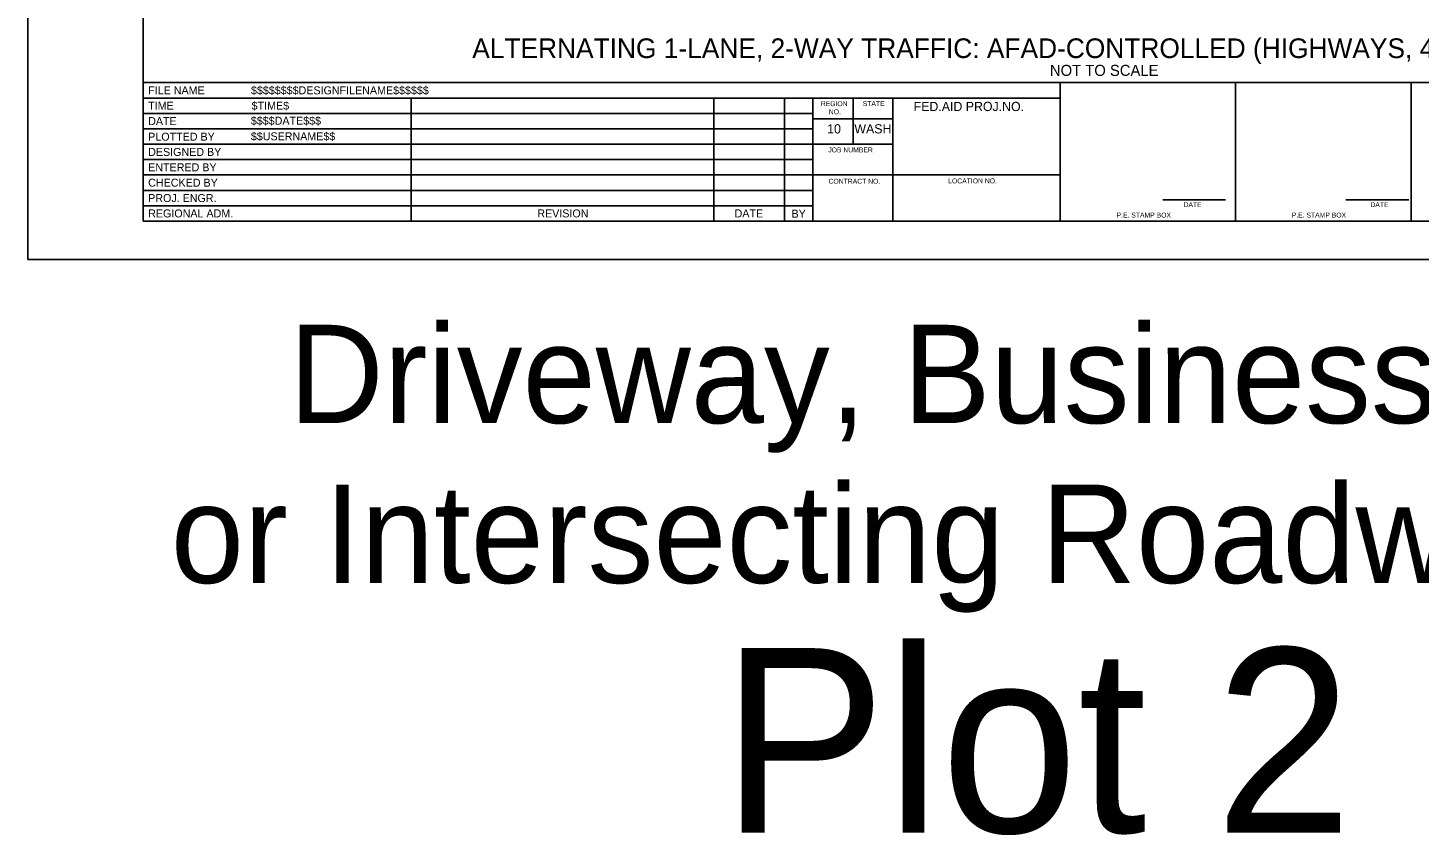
# Model space of a CAD drawing. Extents: x 99999.1 to 100095.7, y 99995 to 100010.7.
# Drawn here: x 100019.06 to 100030.38, y 99995.01 to 100001.57 of the extents above; entities that cross this region are included whole.
import ezdxf

# ---------------------------------------------------------------- set-up
doc = ezdxf.new("R2010")
doc.units = 0
for name, color, linetype in [('SH_DE_DetailHeading1Text', 7, 'Continuous'), ('SH_GI_PlotLimits', 7, 'Continuous'), ('SH_GI_SheetBorder', 7, 'Continuous'), ('SH_GI_SheetLocationText', 7, 'Continuous'), ('SH_GI_SheetTextInCells', 7, 'Continuous'), ('SH_GI_TitleBlockText', 7, 'Continuous')]:
    doc.layers.add(name, color=color, linetype=linetype)

msp = doc.modelspace()

# ---------------------------------------------------------------- linework, layer by layer
at = {"layer": 'SH_GI_PlotLimits'}
msp.add_lwpolyline([(100019.062, 99999.687), (100036.062, 99999.687), (100036.062, 100010.687), (100019.062, 100010.687)], close=True, dxfattribs=at)
at = {"layer": 'SH_GI_SheetBorder'}
for p, q in [((100020, 100010.375), (100020, 100000)), ((100020, 100001.126), (100035.75, 100001.126)), ((100027.457, 100000), (100027.457, 100001.126)), ((100028.883, 100000), (100028.883, 100001.126)), ((100030.309, 100001.126), (100030.309, 100000)), ((100020, 100001.001), (100027.457, 100001.001)), ((100022.179, 100001.001), (100022.179, 100000)), ((100024.641, 100001.001), (100024.641, 100000)), ((100025.216, 100001.001), (100025.216, 100000)), ((100025.445, 100001.001), (100025.445, 100000)), ((100025.772, 100000.625), (100025.772, 100001.001)), ((100026.096, 100000), (100026.096, 100001.001)), ((100020, 100000.876), (100022.182, 100000.876)), ((100022.182, 100000.876), (100025.447, 100000.876)), ((100026.096, 100000.831), (100025.447, 100000.831)), ((100020, 100000.751), (100022.182, 100000.751)), ((100022.182, 100000.751), (100025.447, 100000.751)), ((100020, 100000.625), (100025.447, 100000.625)), ((100026.096, 100000.625), (100025.447, 100000.625)), ((100020, 100000.5), (100025.447, 100000.5)), ((100020, 100000.375), (100025.447, 100000.375)), ((100027.457, 100000.375), (100025.447, 100000.375)), ((100020, 100000.25), (100025.447, 100000.25)), ((100020, 100000.125), (100025.447, 100000.125)), ((100028.29, 100000.173), (100028.802, 100000.173)), ((100029.78, 100000.173), (100030.291, 100000.173)), ((100020, 100000), (100035.75, 100000))]:
    msp.add_line(p, q, dxfattribs=at)

# ---------------------------------------------------------------- texts
at = {"layer": 'SH_DE_DetailHeading1Text'}
for s, height, p in [('ALTERNATING 1-LANE, 2-WAY TRAFFIC: AFAD-CONTROLLED (HIGHWAYS, 40 MPH OR LESS)', 0.16, (100022.676, 100001.326)), ('NOT TO SCALE', 0.09, (100027.373, 100001.181))]:
    msp.add_text(s, height=height, rotation=360, dxfattribs=at).set_placement(p)
at = {"layer": 'SH_GI_SheetLocationText'}
for s, height, p in [('Driveway, Business Access,', 0.8, (100021.184, 99998.357)), ('or Intersecting Roadway Details', 0.8, (100020.225, 99997.057)), ('Plot 2', 1.5, (100024.702, 99995.027))]:
    msp.add_text(s, height=height, dxfattribs=at).set_placement(p)
at = {"layer": 'SH_GI_SheetTextInCells'}
for s, height, p in [('FILE NAME', 0.0651, (100020.041, 100001.031)), ('TIME', 0.0651, (100020.041, 100000.906)), ('REGION', 0.04, (100025.51, 100000.935)), ('NO.', 0.04, (100025.575, 100000.869)), ('STATE', 0.04, (100025.851, 100000.936)), ('FED.AID PROJ.NO.', 0.07506, (100026.265, 100000.895)), ('DATE', 0.0651, (100020.041, 100000.781)), ('10', 0.0751, (100025.562, 100000.713)), ('WASH', 0.0751, (100025.783, 100000.713)), ('PLOTTED BY', 0.0651, (100020.041, 100000.654)), ('DESIGNED BY', 0.06505, (100020.041, 100000.53)), ('JOB NUMBER', 0.04, (100025.571, 100000.559)), ('ENTERED BY', 0.0651, (100020.041, 100000.405)), ('CHECKED BY', 0.0651, (100020.041, 100000.28)), ('CONTRACT NO.', 0.04003, (100025.573, 100000.304)), ('LOCATION NO.', 0.04003, (100026.546, 100000.307)), ('PROJ. ENGR.', 0.06505, (100020.041, 100000.155)), ('REGIONAL ADM.', 0.06505, (100020.041, 100000.03)), ('REVISION', 0.0651, (100023.205, 100000.03)), ('DATE', 0.04, (100028.46, 100000.114)), ('DATE', 0.04, (100029.979, 100000.114)), ('DATE', 0.0651, (100024.809, 100000.03)), ('BY', 0.0651, (100025.272, 100000.028)), ('P.E. STAMP BOX', 0.04003, (100027.915, 100000.029)), ('P.E. STAMP BOX', 0.04003, (100029.339, 100000.029))]:
    msp.add_text(s, height=height, dxfattribs=at).set_placement(p)
at = {"layer": 'SH_GI_TitleBlockText'}
for s, height, p in [('$$$$$$$$DESIGNFILENAME$$$$$$', 0.06505, (100020.877, 100001.031)), ('$TIME$', 0.0651, (100020.882, 100000.906)), ('$$$$DATE$$$', 0.06505, (100020.876, 100000.784)), ('$$USERNAME$$', 0.06505, (100020.876, 100000.657))]:
    msp.add_text(s, height=height, dxfattribs=at).set_placement(p)

doc.saveas('drawing.dxf')
